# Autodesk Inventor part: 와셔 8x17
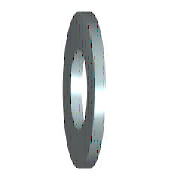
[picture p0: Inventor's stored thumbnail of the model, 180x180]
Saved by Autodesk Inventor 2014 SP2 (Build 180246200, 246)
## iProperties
IsCustomPart: 1
Created: 2012-02
Part Number: 와셔 8x17
Material: 강철, 연강
Description: 평면 와셔
Document SubType Name: Modeling
Standard: KS B 1326
Designer: mduedu
Standards Organization: KS
Language: ko-KR
Size Designation: 8x17
Categories: <MemberInstance><Categories><Category DisplayName="조임쇠" InternalName="e4da775c-781d-43d5-af7c-5136215cf5a6" Mnemonic="FSTN"><Category DisplayName="와셔" InternalN
Density: 1 g/cm^3
Appearance: 주황색
Author: mduedu
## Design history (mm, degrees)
sketch "스케치"
  geometry: C1 r 8.5 at (0, 0); C2 r 4.2 at (0, 0); 1 further point
  constraints: 2 centre point, 2 coincident
  dimensions: "d0" = 8.4 diameter of C2 (= SD1); "d1" = 17 diameter of C1 (= SD2)
extrude "본체" new body sketch "스케치" distance "d2" = 1.6 (= SD); taper "d3" = 0 deg
workaxis "Work Axis1"
workplane "Work Plane1"
body "Solid1"
other parameters: "SD1" = 8.4 [user parameter; used in 1 equation term], "SD2" = 17 [user parameter; used in 1 equation term], "SD" = 1.6 [user parameter; used in 1 equation term], "d4" = 0, "d5" = 0, "d6" = 0, "d7" = 0, "NND" = 8 [user parameter]
